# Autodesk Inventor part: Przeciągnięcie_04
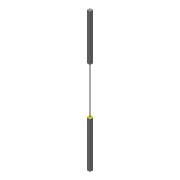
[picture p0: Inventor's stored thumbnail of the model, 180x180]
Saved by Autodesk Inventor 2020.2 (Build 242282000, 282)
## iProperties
Created: 2015-03
Part Number: Przeciągnięcie_04
Material: Ogólny
Document SubType Name: Modeling
Designer: F.Stasiak
Density: 1 g/cm^3
Appearance: Domyślna
Manager: www.cadconsulting.pl
Company: Fabian Stasiak CAD Consulting
Author: F.Stasiak
Subject: Zbiór ćwiczeń. Autodesk Inventor 2020. Kurs podstawowy
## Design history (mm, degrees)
sketch "Szkic1"
  geometry: L1 (-10, 10)-(10, 10); L2 (10, 10)-(10, -10); L3 (10, -10)-(-10, -10); L4 (-10, -10)-(-10, 10); L5 (-10, 10)-(10, -10); L6 (10, 10)-(-10, -10); 1 further point
  constraints: 12 end point, 2 collinear, 2 midpoint, 1 perpendicular, 1 vertical
  dimensions: "d0" = 20 distance of L2.end L3.end; "d1" = 20 distance of L1.end L2.end
extrude "Wyciągnięcie proste1" new body sketch "Szkic1" distance "d2" = 300; taper "d3" = 0 deg
node "Płaszczyzna konstrukcyjna1"
mirror "Odbicie lustrzane1"
sketch "Szkic2"
  geometry: L1 (10, 300)-(-10, 300) reference; L2 (10, 600)-(-10, 600) reference; L3 (0, 300)-(0, 600); 1 further point
  constraints: 2 end point, 2 midpoint
sketch "Szkic3"
  geometry: L1 (10, 10)-(-10, 10) reference; L2 (-10, 10)-(-10, -10) reference; L3 (-10, -10)-(10, -10) reference; L4 (10, -10)-(10, 10) reference; 1 further point
node "Bryła1"
